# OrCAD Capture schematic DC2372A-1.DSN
size Custom
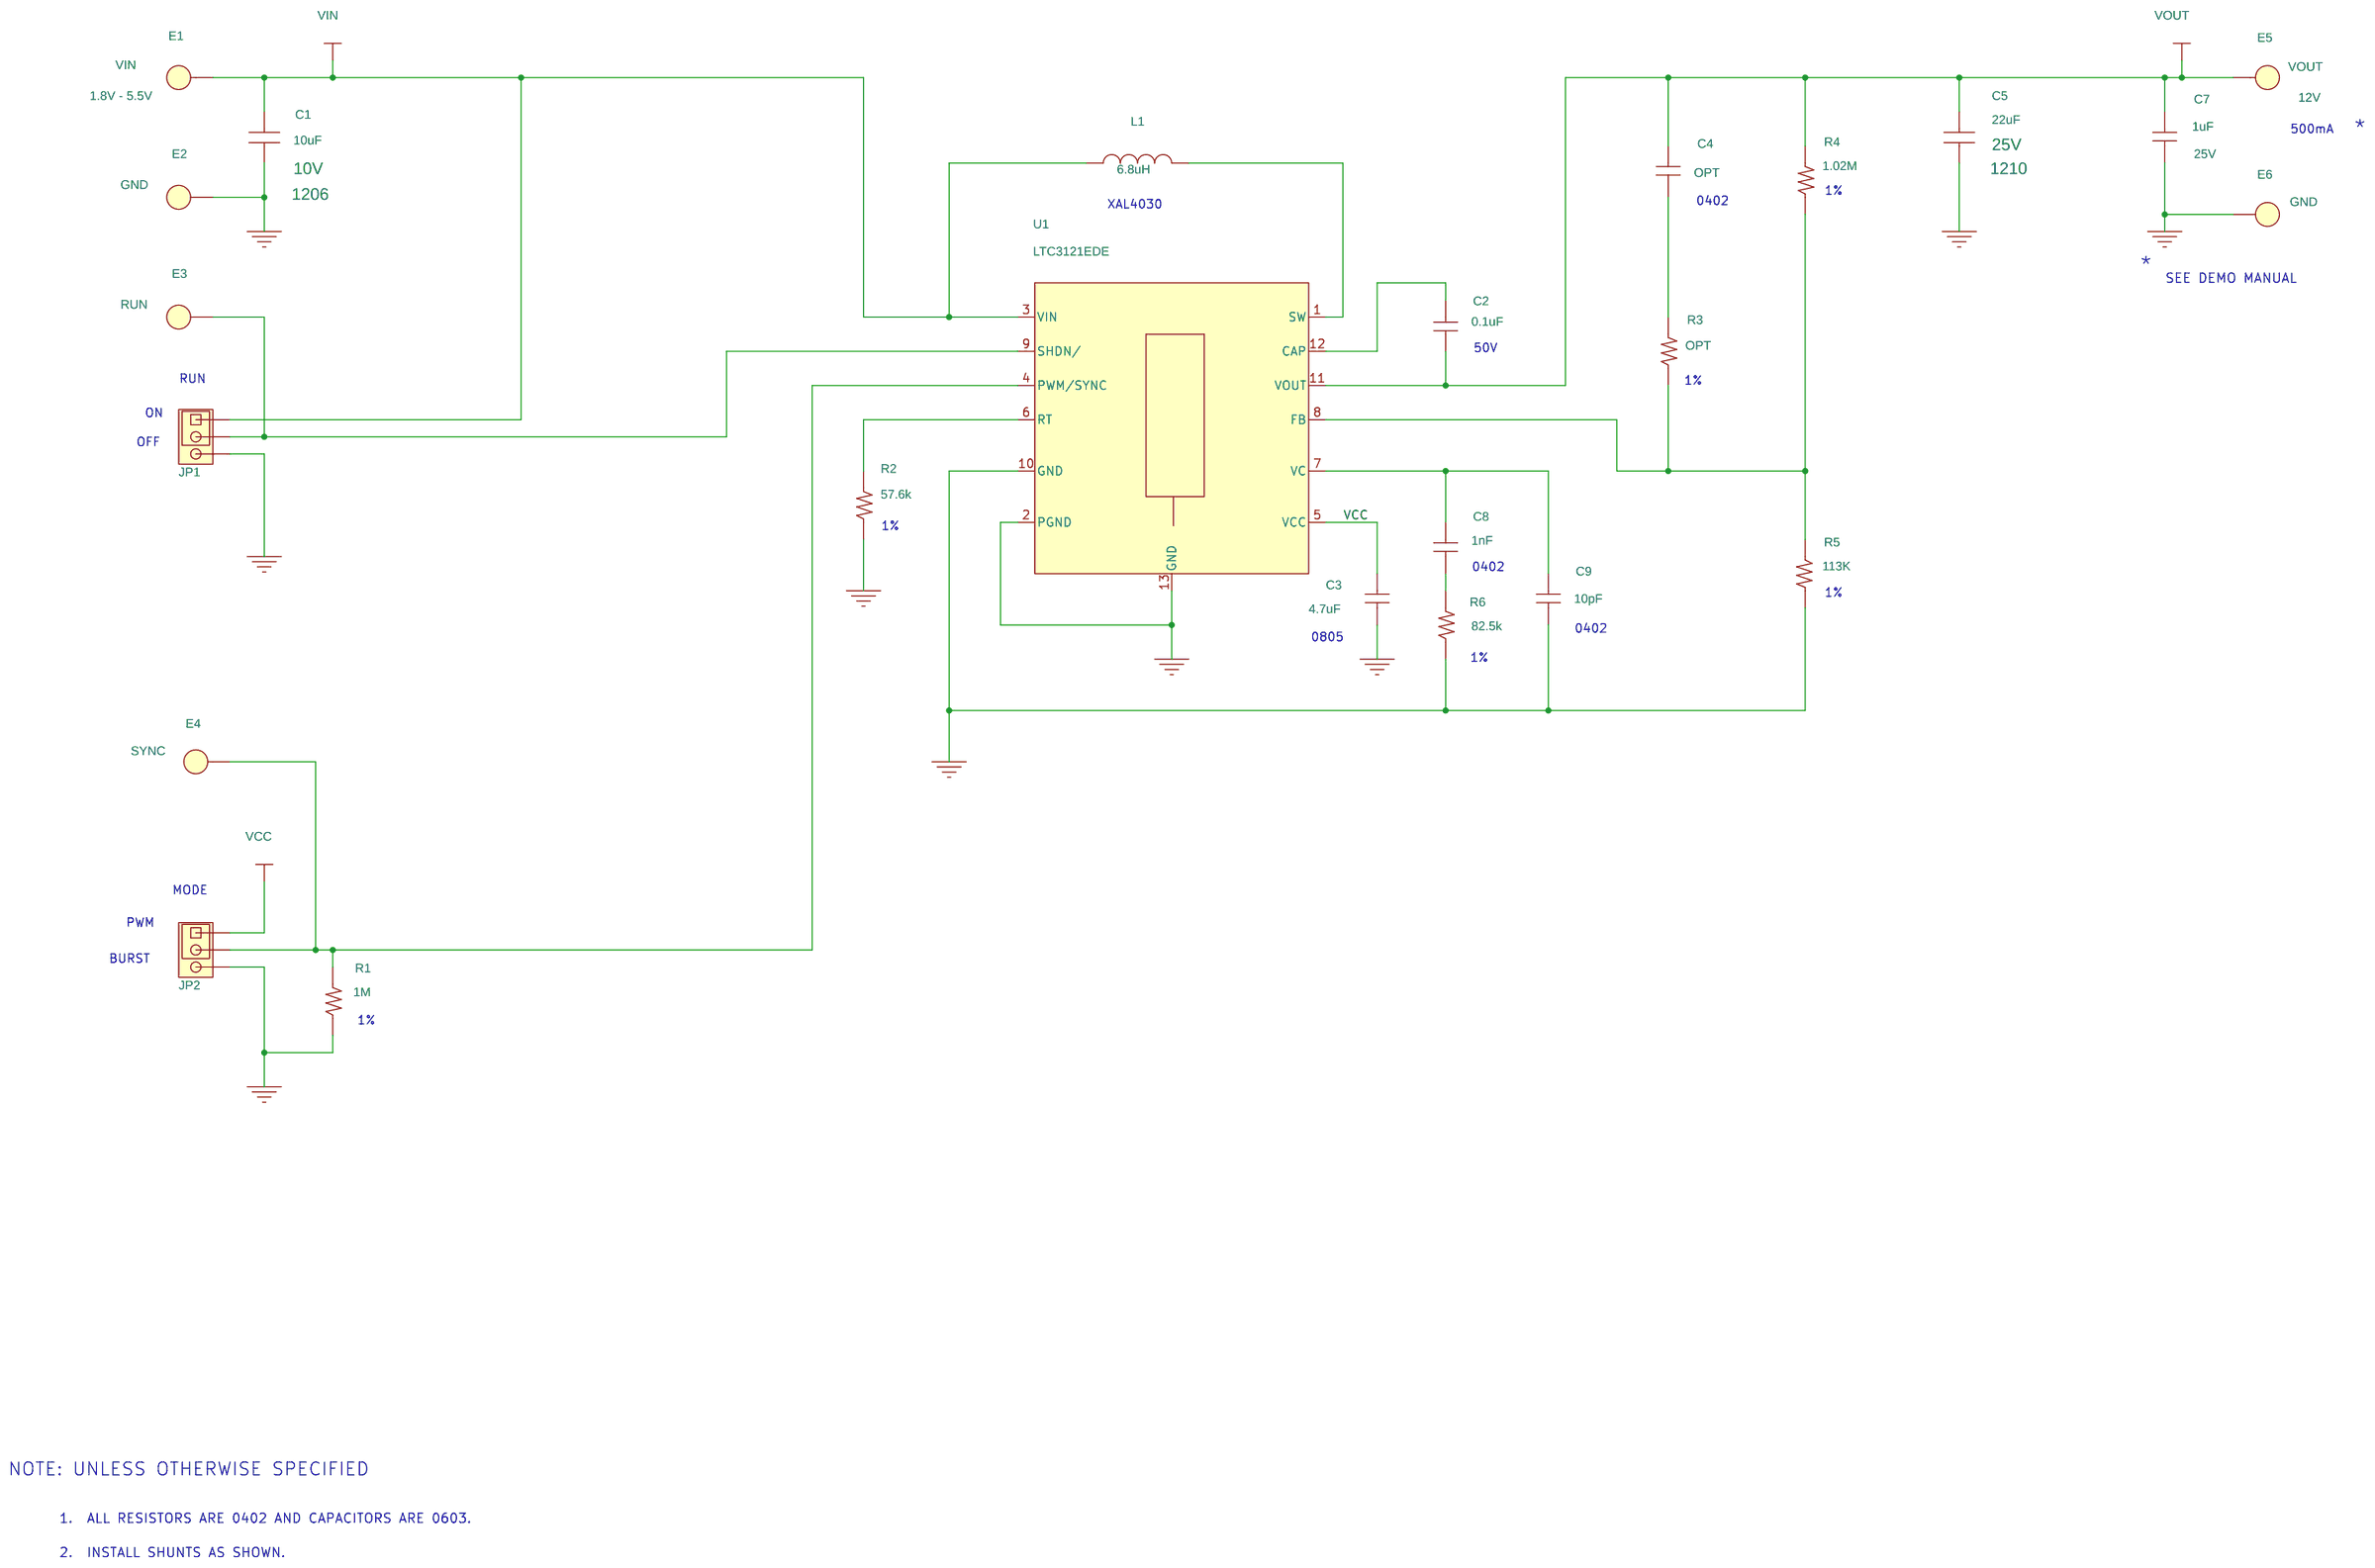
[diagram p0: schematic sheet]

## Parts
C1  10uF  [1206]
C2  0.1uF  [0603]
C3  4.7uF  [0805]
C4  OPT  [0402-SMALL]
C5  22uF  [1210]
C7  1uF  [0603]
C8  1nF  [0402-SMALL]
C9  10pF  [0402-SMALL]
E1  VIN  [MILL-MAX-2501-2]
E2  GND  [MILL-MAX-2501-2]
E3  RUN  [MILL-MAX-2501-2]
E4  SYNC  [MILL-MAX-2501-2]
E5  VOUT  [MILL-MAX-2501-2]
E6  GND  [MILL-MAX-2501-2]
JP1  HD1X3-079  [2MMJUMP3]
JP2  HD1X3-079  [2MMJUMP3]
L1  6.8uH  [IND-XFL4020]
R1  1M  [0402-SMALL]
R2  57.6k  [0402-SMALL]
R3  OPT  [0402-SMALL]
R4  1.02M  [0402-SMALL]
R5  113K  [0402-SMALL]
R6  82.5k  [0402-SMALL]
U1  LTC3121EDE  [DFN(12)4MMX3MM]

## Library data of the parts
C1 = Capacitor_1210: Volt: 10V
C2-C4 C8 C9 = CAP-NP
C5 = Capacitor_1210_1: Volt: 25V
C7 = CAP-NP: VOLT: 25V
E1 = E: v: 1.8V - 5.5V
E2 E3 E6 = E: v: 5V@ 2A
E4 = E: v: 12V / 500mA
E5 = E: v: 12V
JP1 JP2 = HD1X3
L1 = Inductor-XFL4020
R1-R6 = R
U1 = LTC3122_3

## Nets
GND: C1.2 C3.2 C5.2 C7.2 C9.2 E2.1(A) E6.1(A) JP1.3 JP2.3 R1.1 R2.1 R5.2 R6.1 U1.2(PGND) U1.10(GND) U1.13(GND)
VCC: C3.1 JP2.1 U1.5(VCC)
VIN: C1.1 E1.1(A) JP1.1 L1.1 U1.3(VIN)
VOUT: C2.1 C4.1 C5.1 C7.1 E5.1(A) R4.2 U1.11(VOUT)
N17133807: E3.1(A) JP1.2 U1.9(SHDN/)
N17140372: E4.1(A) JP2.2 R1.2 U1.4(PWM/SYNC)
N17147271: C4.2 R3.2
N17149786: R3.1 R4.1 R5.1 U1.8(FB)
N17197138: L1.2 U1.1(SW)
N17198874: C2.2 U1.12(CAP)
N17200392: C8.1 C9.1 U1.7(VC)
N17200417: C8.2 R6.2
N17206411: R2.2 U1.6(RT)

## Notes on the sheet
- 500mA
- *
- 0402
- 1%
- XAL4030
- *
- SEE DEMO MANUAL
- 50V
- RUN
- 1%
- ON
- OFF
- 1%
- 0402
- 1%
- 0805
- 0402
- 1%
- MODE
- PWM
- BURST
- 1%
- NOTE: UNLESS OTHERWISE SPECIFIED
- 1.  ALL RESISTORS ARE 0402 AND CAPACITORS ARE 0603.
- 2.  INSTALL SHUNTS AS SHOWN.
